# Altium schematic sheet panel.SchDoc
size A4
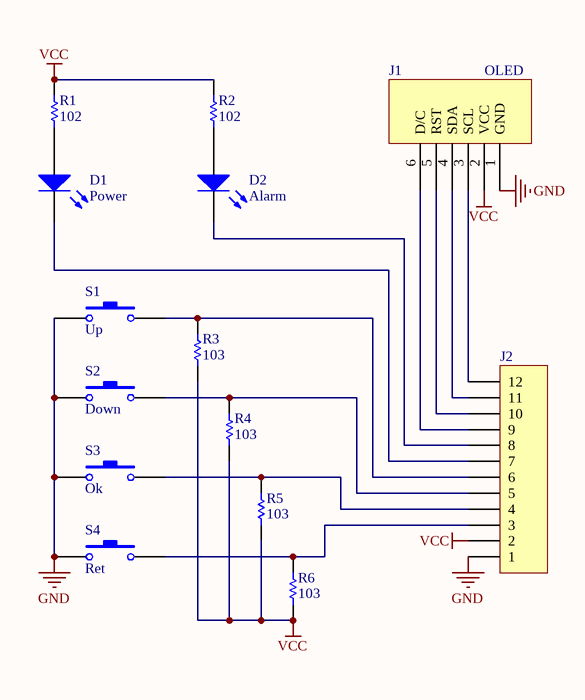
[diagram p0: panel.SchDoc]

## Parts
D1  Power  [LED-2P]
D2  Alarm  [LED-2P]
J1  OLED  [OLED]
J2  (no value)  [XH2.54-12P]
R1  102  [0805]
R2  102  [0805]
R3  103  [0805]
R4  103  [0805]
R5  103  [0805]
R6  103  [0805]
S1  Up  [SW-PB]
S2  Down  [SW-PB]
S3  Ok  [SW-PB]
S4  Ret  [SW-PB]

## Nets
GND: J1.1(GND) J2.1 S1.1 S2.1 S3.1 S4.1
VCC: J1.2(VCC) J2.2 R1.1 R2.2 R3.1 R4.1 R5.1 R6.1
NetD1_1: D1.1(A) R1.2
NetD1_2: D1.2(K) J2.7
NetD2_1: D2.1(A) R2.1
NetD2_2: D2.2(K) J2.8
NetJ1_3: J1.3(SCL) J2.12
NetJ1_4: J1.4(SDA) J2.11
NetJ1_5: J1.5(RST) J2.10
NetJ1_6: J1.6(D/C) J2.9
NetJ2_3: J2.3 R6.2 S4.2
NetJ2_4: J2.4 R5.2 S3.2
NetJ2_5: J2.5 R4.2 S2.2
NetJ2_6: J2.6 R3.2 S1.2

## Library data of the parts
D1 D2 = LED: Typical INFRARED GaAs LED
J2 = Header 12: Header, 12-Pin
R1-R6 = Res: Resistor
S1-S4 = SW-PB: Switch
